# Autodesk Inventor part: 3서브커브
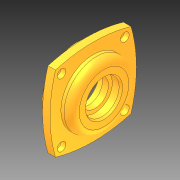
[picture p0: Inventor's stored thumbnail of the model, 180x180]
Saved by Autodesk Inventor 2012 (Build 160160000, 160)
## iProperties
Created: 2012-07
Part Number: 3서브커브
Material: Default
Document SubType Name: Modeling
Designer: JANG KYOUNG-IL
Density: 1 g/cm^3
Author: JANG KYOUNG-IL
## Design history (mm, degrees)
node "작업축1"
node "작업 평면2"
node "작업점1"
sketch "스케치12"
  geometry: L1 (-46.5, 57.5)-(-72.5, 57.5); L2 (-46.5, 90)-(-55.5, 90); L3 (-55.5, 90)-(-55.5, 87.5); L4 (-55.5, 87.5)-(-72.5, 87.5); L5 (-72.5, 87.5)-(-72.5, 73.5); L6 (-72.5, 73.5)-(-64.2, 73.5); L7 (-64.2, 73.5)-(-64.2, 70); L8 (-64.2, 70)-(-58.5, 70); L9 (-58.5, 70)-(-58.5, 77.5); L10 (-58.5, 77.5)-(-46.5, 77.5); L11 (-46.5, 77.5)-(-46.5, 90); 1 further point
  constraints: 22 end point, 8 parallel, 4 point on line, 2 vertical, 1 horizontal
  dimensions: "d87" = 8.3 horizontal distance of L7.end L5.end; "d88" = 12 horizontal distance of L8.end L10.end; "d89" = 25 diameter of L8 L1; "d90" = 32 diameter of L6 L1; "d91" = 40 diameter of L10 L1; "d92" = 65 diameter of L2 L1; "d93" = 60 diameter of L4 L1; "d95" = 9 distance of L2.start L2.end; "d96" = 26 horizontal distance of L4.end L2.start
revolve "회전1" sketch "스케치12" stored, may be unused: angle "d97" = 90 deg
sketch "스케치13"
  geometry: L1 (-35.002, 92.502)-(35.002, 92.502); L2 (35.002, 92.502)-(35.002, 22.498); L3 (35.002, 22.498)-(-35.002, 22.498); L4 (-35.002, 22.498)-(-35.002, 92.502); C1 r 20 at (0, 57.5) reference; A1 r 125.055 centre (0, -27.555) between (35.002, 92.502) and (-35.002, 92.502); A2 r 125.055 centre (0, 142.555) between (-35.002, 22.498) and (35.002, 22.498); A3 r 125.055 centre (85.055, 57.5) between (-35.002, 92.502) and (-35.002, 22.498); A4 r 125.055 centre (-85.055, 57.5) between (35.002, 22.498) and (35.002, 92.502); 4 further points
  constraints: 8 end point, 8 point on circle, 4 centre point, 2 equal radius, 2 midpoint, 2 parallel, 2 perpendicular, 1 horizontal, 1 horizontal alignment, 1 vertical alignment
  dimensions: "d98" = 99 distance of L1.end L3.end; "d99" = 80 dimension on A2 A1; "d100" = 80 dimension on A4 A3
extrude "돌출10" join sketch "스케치13" distance "d101" = 7; taper "d102" = 0 deg
fillet "모깎기7" dims "d103" = 7
chamfer "모따기2" distance "d104" = 2; stored, may be unused: second distance "d105" = 2, angle "d106" = 30 deg
fillet "모깎기8" dims "d107" = 0.3
chamfer "모따기3" distance "d108" = 2; stored, may be unused: second distance "d109" = 2, angle "d110" = 30 deg
sketch "스케치14"
  geometry: L1 (-57.5, 0)-(-99, 0); A1 r 41.5 centre (-57.5, 0) between (-86.845, 29.345) and (-99, 0); 2 further points
  constraints: 2 end point, 2 point on circle, 1 centre point, 1 coincident, 1 horizontal
  dimensions: "d111" = 45 deg dimension on point (-57.5, 0) L1.end A1.start; "d120" = 83 diameter of A1
hole "구멍3" sketch "스케치14" at (-57.5, 0), (-86.845, 29.345) diameter "d112" = 4.5; stored, may be unused: countersink angle "d116" = 90 deg, drill point angle "d118" = 118 deg; dims "d113" = 6, "d114" = 8, "d115" = 4.4, "d117" = 8
node "작업 평면3"
chamfer "모따기4" distance "d121" = 1; stored, may be unused: second distance "d122" = 2, angle "d123" = 45 deg
node "솔리드1"
mirror "대칭3"
mirror "대칭4"
node "솔리드3"
other parameters: "d83" = 55.5, "d119" = 90 deg
